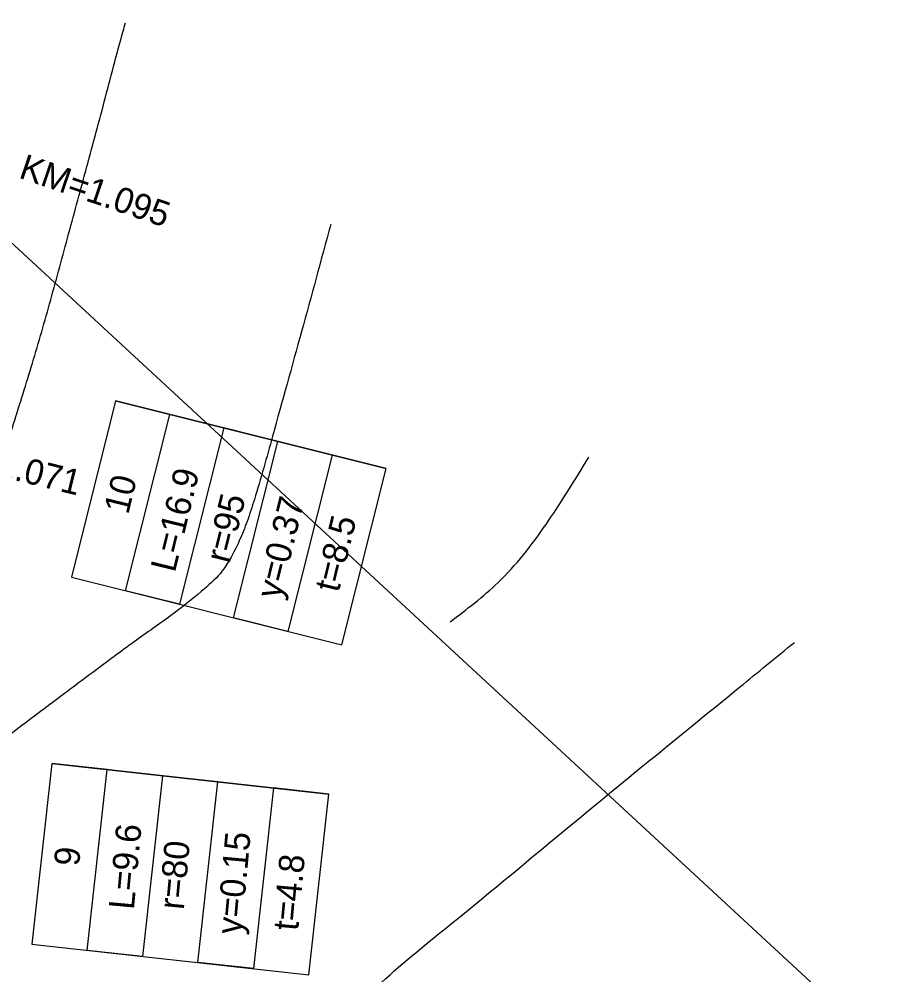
# Model space of a CAD drawing. Extents: x -475575 to -473225, y -1116053 to -1114104.
# Drawn here: x -474309.9 to -474241.7, y -1114513.7 to -1114439 of the extents above; entities that cross this region are included whole.
import ezdxf

# ---------------------------------------------------------------- set-up
doc = ezdxf.new("R2010")
doc.units = 0
for name, color, linetype in [('cesty', 7, 'Continuous'), ('Implicitní', 7, 'Continuous'), ('meliorace', 7, 'Continuous'), ('POLYGONY_SITUACE_PF_POPISY', 7, 'Continuous'), ('TABULKY', 7, 'Continuous'), ('Vrstevnice_vedlejsi', 7, 'Continuous')]:
    doc.layers.add(name, color=color, linetype=linetype)

msp = doc.modelspace()

# ---------------------------------------------------------------- linework, layer by layer
at = {"layer": 'Implicitní'}
msp.add_lwpolyline([(-474392.24, -1114354.32), (-474385.18, -1114363.49), (-474350.25, -1114409.55), (-474320.41, -1114444.98), (-474314.65, -1114451.82), (-474310.64, -1114456.39), (-474234.21, -1114527.12), (-474221.34, -1114539.99), (-474214.34, -1114543), (-474154.82, -1114540.65), (-474095.35, -1114551.68), (-474072.2, -1114553.97), (-474025.99, -1114569.87)], dxfattribs=at)
at = {"layer": 'meliorace'}
for points in [[(-474302.384, -1114468.866), (-474305.835, -1114482.646), (-474284.718, -1114487.935), (-474281.257, -1114474.158)], [(-474307.379, -1114497.212), (-474308.934, -1114511.332), (-474287.295, -1114513.715), (-474285.73, -1114499.596)]]:
    msp.add_lwpolyline(points, close=True, dxfattribs=at)
at = {"layer": 'TABULKY'}
for points in [[(-474302.384, -1114468.866), (-474281.257, -1114474.158), (-474285.478, -1114473.101), (-474288.93, -1114486.88), (-474293.171, -1114485.818), (-474289.719, -1114472.038), (-474293.941, -1114470.981), (-474297.392, -1114484.761), (-474301.614, -1114483.703), (-474298.162, -1114469.923), (-474302.384, -1114468.866), (-474305.835, -1114482.646), (-474284.718, -1114487.935), (-474281.257, -1114474.158)], [(-474307.379, -1114497.212), (-474285.73, -1114499.596), (-474290.056, -1114499.12), (-474291.611, -1114513.24), (-474295.956, -1114512.761), (-474294.401, -1114498.641), (-474298.727, -1114498.165), (-474300.282, -1114512.285), (-474304.608, -1114511.809), (-474303.053, -1114497.688), (-474307.379, -1114497.212), (-474308.934, -1114511.332), (-474287.295, -1114513.715), (-474285.73, -1114499.596)]]:
    msp.add_lwpolyline(points, dxfattribs=at)
at = {"layer": 'Vrstevnice_vedlejsi'}
for points in [[(-474355.556, -1114543.361), (-474352.458, -1114539.678), (-474350.201, -1114536.503), (-474348.784, -1114533.835), (-474348.208, -1114531.674), (-474347.44, -1114529.095), (-474346.48, -1114526.098), (-474345.329, -1114522.683), (-474344.527, -1114519.848), (-474344.072, -1114517.594), (-474343.965, -1114515.921), (-474343.3, -1114513.907), (-474342.078, -1114511.551), (-474340.298, -1114508.855), (-474338.801, -1114506.412), (-474337.589, -1114504.223), (-474336.659, -1114502.288), (-474335.699, -1114500.535), (-474334.708, -1114498.964), (-474333.686, -1114497.575), (-474332.932, -1114496.529), (-474332.448, -1114495.826), (-474332.232, -1114495.464), (-474331.945, -1114495.189), (-474331.587, -1114494.998), (-474331.157, -1114494.893), (-474330.483, -1114494.633), (-474329.567, -1114494.218), (-474328.408, -1114493.648), (-474327.37, -1114493.393), (-474326.453, -1114493.453), (-474325.658, -1114493.828), (-474325.081, -1114494.246), (-474324.724, -1114494.708), (-474324.587, -1114495.213), (-474324.393, -1114495.446), (-474324.142, -1114495.407), (-474323.836, -1114495.095), (-474323.582, -1114494.843), (-474323.379, -1114494.649), (-474323.23, -1114494.514), (-474322.982, -1114494.265), (-474322.637, -1114493.902), (-474322.193, -1114493.424), (-474321.581, -1114492.621), (-474320.8, -1114491.493), (-474319.849, -1114490.041), (-474319.214, -1114489.066), (-474318.892, -1114488.571), (-474318.885, -1114488.553), (-474318.878, -1114488.539), (-474318.869, -1114488.528), (-474318.859, -1114488.519), (-474318.255, -1114487.568), (-474317.055, -1114485.674), (-474315.26, -1114482.837), (-474313.562, -1114479.439), (-474311.96, -1114475.48), (-474310.456, -1114470.96), (-474308.985, -1114466.231), (-474307.548, -1114461.294), (-474306.145, -1114456.148), (-474304.72, -1114450.879), (-474303.271, -1114445.486), (-474301.8, -1114439.969), (-474301.619, -1114439.327)], [(-474285.584, -1114455.09), (-474287.861, -1114463.438), (-474290.127, -1114471.624), (-474291.545, -1114476.573), (-474292.115, -1114478.287), (-474292.723, -1114479.789), (-474293.369, -1114481.08), (-474294.052, -1114482.159), (-474295.443, -1114483.552), (-474297.544, -1114485.257), (-474300.353, -1114487.276), (-474303.516, -1114489.599), (-474307.035, -1114492.227), (-474310.908, -1114495.161), (-474313.678, -1114497.291), (-474315.344, -1114498.619), (-474315.906, -1114499.145), (-474316.394, -1114499.578), (-474316.809, -1114499.918), (-474317.151, -1114500.165), (-474317.506, -1114500.558), (-474317.875, -1114501.096), (-474318.259, -1114501.779), (-474318.669, -1114502.535), (-474319.105, -1114503.365), (-474319.567, -1114504.268), (-474319.903, -1114504.922), (-474320.11, -1114505.325), (-474320.191, -1114505.478), (-474320.349, -1114505.842), (-474320.583, -1114506.416), (-474320.895, -1114507.201), (-474321.122, -1114507.87), (-474321.264, -1114508.425), (-474321.321, -1114508.865), (-474321.357, -1114509.797), (-474321.371, -1114511.221), (-474321.363, -1114513.138), (-474321.709, -1114514.887), (-474322.409, -1114516.468), (-474323.464, -1114517.88), (-474324.278, -1114519.633), (-474324.852, -1114521.728), (-474325.186, -1114524.165), (-474325.75, -1114526.308), (-474326.546, -1114528.159), (-474327.572, -1114529.717), (-474328.814, -1114531.46), (-474330.273, -1114533.386), (-474331.949, -1114535.496), (-474333.023, -1114537.404), (-474333.496, -1114539.107), (-474333.369, -1114540.608), (-474333.308, -1114542.517), (-474333.316, -1114544.833), (-474333.39, -1114547.558), (-474334.649, -1114550.83), (-474337.09, -1114554.649), (-474340.715, -1114559.015), (-474344.384, -1114565.016), (-474348.097, -1114572.652), (-474351.854, -1114581.923), (-474354.717, -1114588.652), (-474356.687, -1114592.838), (-474357.764, -1114594.482), (-474358.075, -1114595.992), (-474357.62, -1114597.368), (-474356.4, -1114598.611), (-474355.953, -1114600.167), (-474356.279, -1114602.036), (-474357.378, -1114604.218), (-474358.428, -1114605.971), (-474359.43, -1114607.294), (-474360.384, -1114608.189), (-474361.122, -1114609.089), (-474361.645, -1114609.996)], [(-474276.253, -1114486.131), (-474272.506, -1114483.066), (-474268.759, -1114478.524), (-474265.415, -1114473.266)], [(-474370.242, -1114755.46), (-474370.143, -1114754.388), (-474370.03, -1114753.444), (-474369.902, -1114752.628), (-474369.758, -1114751.941), (-474369.779, -1114750.9), (-474369.965, -1114749.506), (-474370.315, -1114747.759), (-474370.588, -1114746.346), (-474370.784, -1114745.267), (-474370.904, -1114744.521), (-474371.032, -1114743.681), (-474371.167, -1114742.747), (-474371.311, -1114741.719), (-474371.285, -1114740.759), (-474371.089, -1114739.865), (-474370.724, -1114739.039), (-474370.319, -1114738.151), (-474369.874, -1114737.2), (-474369.39, -1114736.187), (-474368.449, -1114734.378), (-474367.052, -1114731.774), (-474365.198, -1114728.373), (-474363.769, -1114725.694), (-474362.765, -1114723.736), (-474362.187, -1114722.499), (-474361.701, -1114721.187), (-474361.307, -1114719.8), (-474361.004, -1114718.337), (-474360.699, -1114717.01), (-474360.391, -1114715.817), (-474360.08, -1114714.758), (-474358.924, -1114712.244), (-474356.924, -1114708.275), (-474354.079, -1114702.85), (-474351.398, -1114698.199), (-474348.882, -1114694.319), (-474346.53, -1114691.213), (-474344.569, -1114688.436), (-474343, -1114685.987), (-474341.823, -1114683.867), (-474340.569, -1114681.752), (-474339.238, -1114679.641), (-474337.831, -1114677.534), (-474335.985, -1114672.859), (-474333.701, -1114665.616), (-474330.979, -1114655.805), (-474329.274, -1114649.012), (-474328.587, -1114645.238), (-474328.919, -1114644.483), (-474329.063, -1114643.578), (-474329.019, -1114642.525), (-474328.788, -1114641.322), (-474328.335, -1114639.8), (-474327.66, -1114637.959), (-474326.762, -1114635.799), (-474325.513, -1114632.736), (-474323.91, -1114628.771), (-474321.955, -1114623.904), (-474320.056, -1114619.053), (-474318.212, -1114614.216), (-474316.424, -1114609.395), (-474315.076, -1114605.754), (-474314.17, -1114603.291), (-474313.705, -1114602.008), (-474313.056, -1114599.982), (-474312.224, -1114597.214), (-474311.208, -1114593.704), (-474309.119, -1114588.008), (-474305.955, -1114580.129), (-474301.718, -1114570.064), (-474298.467, -1114561.838), (-474296.203, -1114555.45), (-474294.926, -1114550.901), (-474293.186, -1114544.94), (-474290.982, -1114537.567), (-474288.316, -1114528.784), (-474286.496, -1114522.666), (-474285.522, -1114519.213), (-474285.395, -1114518.427), (-474285.261, -1114517.866), (-474285.118, -1114517.531), (-474284.969, -1114517.423), (-474284.333, -1114516.85), (-474283.212, -1114515.813), (-474281.606, -1114514.311), (-474276.141, -1114509.715), (-474266.818, -1114502.025), (-474253.636, -1114491.24), (-474249.353, -1114487.74)]]:
    msp.add_spline(points, degree=3, dxfattribs=at)

# ---------------------------------------------------------------- texts
at = {"layer": 'cesty'}
for s, height, rotation, p in [('L=16.9', 1.9765, 76.26603, (-474297.762, -1114482.341)), ('10', 1.9765, 76.26603, (-474301.406, -1114477.808)), ('r=95', 1.9765, 76.26603, (-474293.483, -1114481.628)), ('y=0.37', 1.9765, 76.26603, (-474289.524, -1114484.428)), ('t=8.5', 1.9765, 76.26603, (-474284.964, -1114483.895)), ('L=9.6', 1.9765, 84.80238, (-474300.961, -1114508.678)), ('r=80', 1.9765, 84.80238, (-474297.062, -1114508.679)), ('y=0.15', 1.9765, 84.80238, (-474292.555, -1114510.614)), ('9', 1.976, 84.80238, (-474305.245, -1114505.278)), ('t=4.8', 1.9765, 84.80238, (-474288.132, -1114510.316))]:
    msp.add_text(s, height=height, rotation=rotation, dxfattribs=at).set_placement(p)
at = {"layer": 'POLYGONY_SITUACE_PF_POPISY'}
for s, rotation, p in [('KM=1.095', 341.17998, (-474310.036, -1114451.41)), ('KM=1.071', 346.26603, (-474317.162, -1114473.387))]:
    msp.add_text(s, height=1.9765, rotation=rotation, dxfattribs=at).set_placement(p)

doc.saveas('drawing.dxf')
